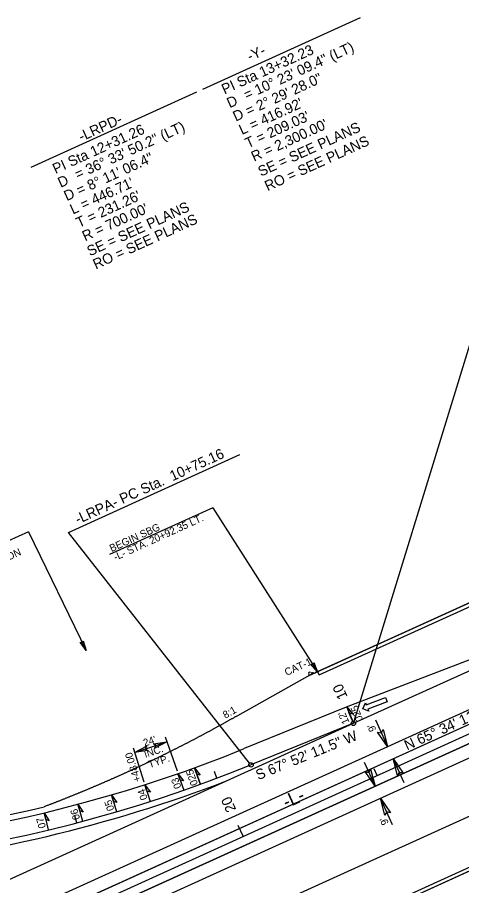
# Model space of a CAD drawing. Extents: x 2242984 to 2250974, y 661492 to 664681.
# Drawn here: x 2248440 to 2248742, y 663168 to 663758 of the extents above; entities that cross this region are included whole.
import ezdxf

# ---------------------------------------------------------------- set-up
doc = ezdxf.new("R2010")
doc.units = 0
for name, color, linetype in [('Prop Conc Shoulder Berm Gutter', 7, 'Continuous'), ('Prop Dimension', 7, 'Continuous'), ('Prop Dimension Text', 7, 'Continuous'), ('Prop DSN Text', 7, 'Continuous'), ('Prop EOT', 7, 'Continuous'), ('Prop Guardrail', 7, 'Continuous'), ('Prop Guardrail Anchor Unit CELL', 7, 'Continuous'), ('Prop Horizontal Alignment', 7, 'Continuous'), ('Prop Horizontal Alignment Curve and Spiral Data', 7, 'Continuous'), ('Prop Horizontal Alignment Direction Label', 7, 'Continuous'), ('Prop Horizontal Alignment Station Label', 7, 'Continuous'), ('Prop Horizontal Alignment Tick Label', 7, 'Continuous'), ('Prop Horizontal Alignment Tick Large', 7, 'Continuous'), ('Prop Horizontal Alignment Tick Small', 7, 'Continuous'), ('Prop Lane Arrow CELL', 7, 'Continuous'), ('Prop Lane Lines', 7, 'Continuous'), ('Prop Paved Shoulder', 7, 'Continuous'), ('Prop Superelevation  Arrow CELL', 7, 'Continuous'), ('Prop Superelevation Label', 7, 'Continuous'), ('Prop Terminator CELL', 7, 'Continuous'), ('Scratch_Level_6', 7, 'Continuous'), ('Scratch_Level_8', 7, 'Continuous'), ('Typical Terminator CELL', 7, 'Continuous')]:
    doc.layers.add(name, color=color, linetype=linetype)

# ---------------------------------------------------------------- blocks, each defined once
blk = doc.blocks.new('TERMINATOR')
at = {"layer": 'Typical Terminator CELL'}
blk.add_lwpolyline([(-0.469, 0.081), (0, 0), (-0.471, -0.083), (-0.411, 0)], close=True, dxfattribs=at)

msp = doc.modelspace()

# ---------------------------------------------------------------- linework, layer by layer
at = {"layer": 'Prop Conc Shoulder Berm Gutter'}
for p, q in [((2248644.9, 663311.13), (2248856.16, 663407.1)), ((2248643.94, 663313.26), (2248644.9, 663311.13)), ((2248645.24, 663134.09), (2248878.26, 663239.94))]:
    msp.add_line(p, q, dxfattribs=at)
at = {"layer": 'Prop Dimension'}
for p, q in [((2248668.27, 663278.18), (2248663.75, 663289.3)), ((2248683.23, 663280.59), (2248691.5, 663262.37)), ((2248540.32, 663268.91), (2248548.38, 663245.78)), ((2248518.51, 663261.48), (2248525.92, 663238.35)), ((2248702.68, 663237.75), (2248695.22, 663254.18)), ((2248675.51, 663251.85), (2248682.97, 663235.43)), ((2248694.89, 663209.19), (2248686.69, 663227.24))]:
    msp.add_line(p, q, dxfattribs=at)
msp.add_arc((2248237.01, 664139.15), 925, 287.78265, 289.21505, dxfattribs=at)
at = {"layer": 'Prop DSN Text'}
for p, q in [((2248572.63, 663424.84), (2248502.57, 663392.92)), ((2248572.63, 663424.84), (2248643.94, 663313.26)), ((2248447.47, 663408.55), (2248359.33, 663368.39)), ((2248447.47, 663408.55), (2248486.57, 663327.68))]:
    msp.add_line(p, q, dxfattribs=at)
at = {"layer": 'Prop EOT'}
for p, q in [((2248200.21, 663039.2), (2249433.89, 663599.6)), ((2248212.61, 663011.89), (2249446.3, 663572.29)), ((2248401.88, 663058.32), (2249188.04, 663415.44)), ((2248850.37, 663360.9), (2248663.29, 663289.12)), ((2248663.3, 663289.11), (2248594.13, 663260.98))]:
    msp.add_line(p, q, dxfattribs=at)
msp.add_arc((2248237.01, 664139.15), 948, 264.58168, 292.13013, dxfattribs=at)
at = {"layer": 'Prop Guardrail'}
for p, q in [((2248871.49, 663416.62), (2248643.94, 663313.26)), ((2248855.32, 663313.72), (2247994.71, 662922.79)), ((2248855.32, 663313.72), (2247994.71, 662922.79)), ((2247989.75, 662933.71), (2248810.53, 663306.55)), ((2247989.75, 662933.71), (2248810.53, 663306.55)), ((2248646.2, 663131.96), (2248885.14, 663240.5))]:
    msp.add_line(p, q, dxfattribs=at)
at = {"layer": 'Prop Guardrail Anchor Unit CELL'}
for p, q in [((2248639.22, 663312.85), (2248640.18, 663312.32)), ((2248640.14, 663312.42), (2248640.77, 663312.71)), ((2248640.47, 663311.68), (2248640.77, 663312.71)), ((2248643.94, 663313.26), (2248640.71, 663311.79)), ((2248640.77, 663312.71), (2248641.11, 663311.97)), ((2248642.97, 663313.7), (2248643.61, 663313.99)), ((2248643.3, 663312.97), (2248642.97, 663313.7)), ((2248643.94, 663313.26), (2248642.97, 663313.7)), ((2248643.3, 663312.97), (2248643.61, 663313.99)), ((2248643.94, 663313.26), (2248643.3, 663312.97)), ((2248643.61, 663313.99), (2248643.94, 663313.26)), ((2248640.71, 663311.79), (2248639.15, 663311.08)), ((2248640.47, 663311.68), (2248640.14, 663312.42)), ((2248641.11, 663311.97), (2248640.14, 663312.42)), ((2248641.11, 663311.97), (2248640.47, 663311.68)), ((2248640.59, 663311.74), (2248640.71, 663311.79)), ((2248640.62, 663312.19), (2248642.52, 663312.61))]:
    msp.add_line(p, q, dxfattribs=at)
msp.add_ellipse((2248638.74, 663311.99), major_axis=(0.411, -0.904), ratio=0.995379, start_param=2.210226, end_param=6.283185, dxfattribs=at)
at = {"layer": 'Prop Horizontal Alignment'}
for p, q in [((2247500.8, 662705.02), (2249793.08, 663746.29)), ((2248668.27, 663278.18), (2248598.65, 663249.87))]:
    msp.add_line(p, q, dxfattribs=at)
msp.add_arc((2248237.01, 664139.15), 960, 261.59641, 292.13013, dxfattribs=at)
at = {"layer": 'Prop Horizontal Alignment Station Label'}
for p, q in [((2248565.88, 663709.6), (2248673.03, 663758.42)), ((2248449.37, 663656.46), (2248561.96, 663707.76)), ((2248668.71, 663279.62), (2248748.29, 663538.62)), ((2248474.68, 663408.03), (2248591, 663461.04)), ((2248597.73, 663251.05), (2248474.68, 663408.03))]:
    msp.add_line(p, q, dxfattribs=at)
for centre in [(2248668.27, 663278.18), (2248598.65, 663249.87)]:
    msp.add_circle(centre, 1.5, dxfattribs=at)
at = {"layer": 'Prop Horizontal Alignment Tick Large'}
for p, q in [((2248668.27, 663278.18), (2248665.26, 663285.59)), ((2248593.36, 663201.31), (2248590.05, 663208.6))]:
    msp.add_line(p, q, dxfattribs=at)
at = {"layer": 'Prop Horizontal Alignment Tick Small'}
for p, q in [((2248575.52, 663240.81), (2248573.76, 663245.49)), ((2248684.4, 663242.67), (2248682.34, 663247.23)), ((2248480.28, 663210.48), (2248479.01, 663215.32))]:
    msp.add_line(p, q, dxfattribs=at)
at = {"layer": 'Prop Lane Arrow CELL'}
for p, q in [((2248677, 663290.82), (2248690.1, 663295.76)), ((2248690.1, 663295.76), (2248691.26, 663292.68)), ((2248674.65, 663288.11), (2248676.47, 663292.22)), ((2248676.47, 663292.22), (2248677, 663290.82)), ((2248691.26, 663292.68), (2248678.17, 663287.73)), ((2248678.7, 663286.33), (2248674.65, 663288.11)), ((2248678.17, 663287.73), (2248678.7, 663286.33))]:
    msp.add_line(p, q, dxfattribs=at)
at = {"layer": 'Prop Lane Lines'}
for p, q in [((2248668.27, 663278.18), (2248850.37, 663360.9)), ((2248304.14, 663112.77), (2248668.27, 663278.18))]:
    msp.add_line(p, q, dxfattribs=at)
msp.add_arc((2248237.01, 664139.15), 964, 275.75472, 290.97015, dxfattribs=at)
at = {"layer": 'Prop Paved Shoulder'}
for p, q in [((2248638.25, 663310.67), (2248855.2, 663409.22)), ((2248203.91, 663031), (2248894.79, 663344.83)), ((2248208.89, 663020.08), (2248895.78, 663332.1)), ((2248646.2, 663131.96), (2248879.23, 663237.81))]:
    msp.add_line(p, q, dxfattribs=at)
msp.add_arc((2248237.01, 664139.15), 944, 264.58097, 283.54456, dxfattribs=at)
for points in [[(2248638.25, 663310.67), (2248637.45, 663310.22), (2248636.64, 663309.77), (2248635.84, 663309.32), (2248635.03, 663308.87), (2248634.22, 663308.42), (2248633.42, 663307.97), (2248632.61, 663307.52), (2248631.81, 663307.06), (2248631, 663306.61), (2248630.19, 663306.16), (2248629.39, 663305.71), (2248628.58, 663305.26), (2248627.78, 663304.81), (2248626.97, 663304.36), (2248626.17, 663303.91), (2248625.36, 663303.45), (2248624.55, 663303), (2248623.75, 663302.55), (2248622.94, 663302.1), (2248622.14, 663301.65), (2248621.33, 663301.2), (2248620.53, 663300.75), (2248619.72, 663300.3), (2248618.91, 663299.84), (2248618.11, 663299.39), (2248617.3, 663298.94), (2248616.5, 663298.49), (2248615.69, 663298.04), (2248614.89, 663297.59), (2248614.08, 663297.14), (2248613.27, 663296.69), (2248612.47, 663296.23), (2248611.66, 663295.78), (2248610.86, 663295.33), (2248610.05, 663294.88), (2248609.24, 663294.43), (2248608.44, 663293.98), (2248607.63, 663293.53), (2248606.83, 663293.08), (2248606.02, 663292.62), (2248605.22, 663292.17), (2248604.41, 663291.72), (2248603.6, 663291.27), (2248602.8, 663290.82), (2248601.99, 663290.37), (2248601.19, 663289.92), (2248600.38, 663289.47), (2248599.58, 663289.01), (2248598.77, 663288.56), (2248597.96, 663288.11), (2248597.16, 663287.66), (2248596.35, 663287.21), (2248595.55, 663286.76), (2248594.74, 663286.31), (2248593.94, 663285.86), (2248593.13, 663285.4), (2248592.32, 663284.95), (2248591.52, 663284.5), (2248590.71, 663284.05), (2248589.91, 663283.6), (2248589.1, 663283.15), (2248588.29, 663282.7), (2248587.49, 663282.25), (2248586.68, 663281.79), (2248585.88, 663281.34), (2248585.1, 663280.9), (2248584.32, 663280.47), (2248583.55, 663280.03), (2248582.77, 663279.59), (2248581.99, 663279.16), (2248581.21, 663278.72), (2248580.43, 663278.29), (2248579.65, 663277.85), (2248578.87, 663277.42)], [(2248578.87, 663277.42), (2248578.09, 663276.99), (2248577.31, 663276.56), (2248576.53, 663276.13), (2248575.75, 663275.69), (2248574.97, 663275.27), (2248574.18, 663274.84), (2248573.4, 663274.41), (2248572.61, 663273.98), (2248571.83, 663273.55), (2248571.04, 663273.13), (2248570.26, 663272.7), (2248569.47, 663272.28), (2248568.69, 663271.85), (2248567.9, 663271.43), (2248567.11, 663271.01), (2248566.32, 663270.59), (2248565.53, 663270.17), (2248564.74, 663269.75), (2248563.95, 663269.33), (2248563.16, 663268.91), (2248562.37, 663268.49), (2248561.58, 663268.07), (2248560.79, 663267.66), (2248560, 663267.24), (2248559.21, 663266.82), (2248558.41, 663266.41), (2248557.62, 663266), (2248556.82, 663265.58), (2248556.03, 663265.17), (2248555.23, 663264.76), (2248554.44, 663264.35), (2248553.64, 663263.94), (2248552.85, 663263.53), (2248552.05, 663263.12), (2248551.25, 663262.71), (2248550.45, 663262.3), (2248549.65, 663261.9), (2248548.85, 663261.49), (2248548.05, 663261.09), (2248547.25, 663260.68), (2248546.45, 663260.28), (2248545.65, 663259.87), (2248544.85, 663259.47), (2248544.05, 663259.07), (2248543.25, 663258.67), (2248542.44, 663258.27), (2248541.64, 663257.87), (2248540.83, 663257.47), (2248540.03, 663257.07), (2248539.23, 663256.68), (2248538.42, 663256.28), (2248537.61, 663255.88), (2248536.81, 663255.49), (2248536, 663255.1), (2248535.19, 663254.7), (2248534.38, 663254.31), (2248533.58, 663253.92), (2248532.77, 663253.53), (2248531.96, 663253.14), (2248531.15, 663252.75), (2248530.34, 663252.36), (2248529.53, 663251.97), (2248528.72, 663251.58), (2248527.9, 663251.19), (2248527.09, 663250.81), (2248526.28, 663250.42), (2248525.47, 663250.04), (2248524.65, 663249.65), (2248523.84, 663249.27), (2248523.02, 663248.89), (2248522.21, 663248.51), (2248521.39, 663248.13), (2248520.58, 663247.75), (2248519.76, 663247.37)], [(2248519.76, 663247.37), (2248518.94, 663246.99), (2248518.13, 663246.61), (2248517.31, 663246.23), (2248516.49, 663245.86), (2248515.67, 663245.48), (2248514.85, 663245.11), (2248514.03, 663244.73), (2248513.21, 663244.36), (2248512.39, 663243.99), (2248511.57, 663243.61), (2248510.75, 663243.24), (2248509.93, 663242.87), (2248509.1, 663242.5), (2248508.28, 663242.13), (2248507.46, 663241.77), (2248506.63, 663241.4), (2248505.81, 663241.03), (2248504.99, 663240.67), (2248504.16, 663240.3), (2248503.33, 663239.94), (2248502.51, 663239.57), (2248501.68, 663239.21), (2248500.86, 663238.85), (2248500.03, 663238.49), (2248499.2, 663238.13), (2248498.37, 663237.77), (2248497.54, 663237.41), (2248496.71, 663237.05), (2248495.88, 663236.69), (2248495.05, 663236.34), (2248494.22, 663235.98), (2248493.39, 663235.62), (2248492.56, 663235.27), (2248491.73, 663234.92), (2248490.9, 663234.56), (2248490.06, 663234.21), (2248489.23, 663233.86), (2248488.4, 663233.51), (2248487.56, 663233.16), (2248486.73, 663232.81), (2248485.89, 663232.46), (2248485.06, 663232.11), (2248484.22, 663231.77), (2248483.39, 663231.42), (2248482.55, 663231.08), (2248481.71, 663230.73), (2248480.87, 663230.39), (2248480.04, 663230.04), (2248479.2, 663229.7), (2248478.36, 663229.36), (2248477.52, 663229.02), (2248476.68, 663228.68), (2248475.84, 663228.34), (2248475, 663228), (2248474.16, 663227.67), (2248473.32, 663227.33), (2248472.47, 663226.99), (2248471.63, 663226.66), (2248470.79, 663226.32), (2248469.95, 663225.99), (2248469.1, 663225.66), (2248468.26, 663225.32), (2248467.41, 663224.99), (2248466.57, 663224.66), (2248465.72, 663224.33), (2248464.88, 663224), (2248464.03, 663223.68), (2248463.19, 663223.35), (2248462.34, 663223.02), (2248461.49, 663222.7), (2248460.64, 663222.37), (2248459.79, 663222.05), (2248458.1, 663221.4)]]:
    msp.add_spline(points, degree=3, dxfattribs=at)
at = {"layer": 'Prop Superelevation  Arrow CELL'}
for p, q in [((2248663.75, 663289.3), (2248668.27, 663278.18)), ((2248560.18, 663247.93), (2248564.27, 663236.65)), ((2248549.01, 663243.96), (2248552.96, 663232.63)), ((2248526.54, 663236.44), (2248530.2, 663225.01)), ((2248503.88, 663229.48), (2248507.26, 663217.97)), ((2248481.06, 663223.1), (2248484.15, 663211.5)), ((2248458.08, 663217.28), (2248460.88, 663205.61))]:
    msp.add_line(p, q, dxfattribs=at)
for points in [[(2248663.75, 663289.3), (2248667.87, 663284.49), (2248665.5, 663285.01)], [(2248560.18, 663247.93), (2248564.1, 663242.97), (2248561.75, 663243.58)], [(2248549.01, 663243.96), (2248552.87, 663238.95), (2248550.53, 663239.59)], [(2248526.54, 663236.44), (2248530.27, 663231.34), (2248527.95, 663232.04)], [(2248503.88, 663229.48), (2248507.49, 663224.29), (2248505.18, 663225.05)], [(2248481.06, 663223.1), (2248484.54, 663217.81), (2248482.25, 663218.63)], [(2248458.08, 663217.28), (2248461.43, 663211.92), (2248459.16, 663212.79)]]:
    msp.add_lwpolyline(points, close=True, dxfattribs=at)
at = {"layer": 'Prop Superelevation Label'}
msp.add_line((2248564.27, 663236.65), (2248560.18, 663247.93), dxfattribs=at)
at = {"layer": 'Prop Terminator CELL'}
for points in [[(2248484.68, 663334.26), (2248486.57, 663327.68), (2248482.54, 663333.27), (2248483.99, 663333.01)], [(2248641.28, 663319.57), (2248643.94, 663313.26), (2248639.27, 663318.33), (2248640.75, 663318.25)], [(2248532.43, 663264.22), (2248541.44, 663265.68), (2248533.4, 663261.22), (2248533.97, 663263.11)], [(2248528.55, 663259.65), (2248519.51, 663258.34), (2248527.62, 663262.66), (2248527.02, 663260.79)]]:
    msp.add_lwpolyline(points, close=True, dxfattribs=at)
at = {"layer": 'Scratch_Level_6'}
for p, q in [((2248643.9, 663313.35), (2248888.59, 663424.5)), ((2248639.11, 663311.17), (2248643.9, 663313.35)), ((2248902.31, 663248.19), (2248646.24, 663131.87))]:
    msp.add_line(p, q, dxfattribs=at)
at = {"layer": 'Scratch_Level_8'}
for p, q in [((2248643.9, 663313.34), (2248866.79, 663414.59)), ((2248880.54, 663238.31), (2248646.24, 663131.88))]:
    msp.add_line(p, q, dxfattribs=at)

# ---------------------------------------------------------------- block references
at = {"layer": 'Prop Dimension', "xscale": 25}
for p, yscale, rotation in [((2248691.5, 663262.37), 25, -65.56987410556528), ((2248695.22, 663254.18), 25.00000000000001, 114.43012589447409), ((2248682.97, 663235.43), 25, -65.56987410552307), ((2248686.69, 663227.24), 25, 114.43012589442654)]:
    msp.add_blockref('TERMINATOR', p, dxfattribs=dict(at, yscale=yscale, rotation=rotation))

# ---------------------------------------------------------------- texts
at = {"layer": 'Prop Dimension'}
for s, rotation, p in [("9'", 114.43013, (2248683.99, 663273.79)), ("24'", 18.49885, (2248526.37, 663262.35)), ('INC.', 18.49885, (2248526.89, 663254.61)), ('+48.00', 107.78265, (2248523.96, 663239.25)), ('TYP.', 18.49885, (2248529.81, 663247.68)), ("9'", 114.43013, (2248692.42, 663210.3))]:
    msp.add_text(s, height=5, rotation=rotation, dxfattribs=at).set_placement(p)
at = {"layer": 'Prop Dimension Text'}
for s, rotation, p in [('8:1', 29.24602, (2248581.23, 663281.23)), ("12'", 114.49794, (2248665.71, 663278.95))]:
    msp.add_text(s, height=5, rotation=rotation, dxfattribs=at).set_placement(p)
at = {"layer": 'Prop DSN Text'}
for s, p in [('-L- STA. 20+92.35 LT.', (2248506.62, 663388.7)), ('BEGIN SBG', (2248503.9, 663394.66)), ('DURING CONSTRUCTION', (2248368.26, 663358.92))]:
    msp.add_text(s, height=5, rotation=24.49794, dxfattribs=at).set_placement(p)
at = {"layer": 'Prop Guardrail Anchor Unit CELL'}
msp.add_text('CAT-1', height=5, rotation=24.43013, dxfattribs=at).set_placement((2248622.88, 663310.36))
at = {"layer": 'Prop Horizontal Alignment Curve and Spiral Data'}
for s, height, rotation, p in [('PI Sta 13+32.23', 7, 24.49794, (2248580.64, 663705.94)), ('= 10%%d 23\' 09.4" (LT)', 7, 24.49794, (2248595.74, 663702.16)), ('-Y-', 7, 24.49794, (2248597.89, 663728.38)), ('D = 2%%d 29\' 28.0"', 7, 24.49794, (2248588.32, 663687.46)), ('D', 7, 24.49794, (2248584.17, 663696.56)), ("L = 416.92'", 7, 24.49794, (2248592.47, 663678.36)), ('-LRPD-', 7, 24.49794, (2248483.4, 663673.8)), ("T = 209.03'", 7, 24.49794, (2248596.61, 663669.26)), ('PI Sta 12+31.26', 7, 24.49794, (2248465.78, 663651.82)), ('= 36%%d 33\' 50.2" (LT)', 7, 24.49794, (2248480.88, 663648.04)), ("R = 2,300.00'", 7, 24.49794, (2248600.76, 663660.16)), ('SE = SEE PLANS', 7, 24.49794, (2248605.4, 663649.99)), ('RO = SEE PLANS', 7, 24.49794, (2248609.91, 663640.09)), ('D = 8%%d 11\' 06.4"', 7, 24.49794, (2248473.46, 663633.34)), ('D', 7, 24.49794, (2248469.31, 663642.44)), ("L = 446.71'", 7, 24.49794, (2248477.61, 663624.24)), ("T = 231.26'", 7, 24.49794, (2248481.75, 663615.14)), ("R = 700.00'", 7, 24.49794, (2248485.9, 663606.04)), ('SE = SEE PLANS', 7, 24.49794, (2248489.15, 663595.79)), ('RO = SEE PLANS', 7, 24.49794, (2248493.21, 663586.87)), ('-L-', 9, 24.43013, (2248622.69, 663220.12))]:
    msp.add_text(s, height=height, rotation=rotation, dxfattribs=at).set_placement(p)
at = {"layer": 'Prop Horizontal Alignment Direction Label'}
for s, rotation, p in [('N 65%%d 34\' 11.5" E', 24.43013, (2248704.77, 663259.62)), ('S 67%%d 52\' 11.5" W', 22.13013, (2248603.61, 663239.45))]:
    msp.add_text(s, height=7, rotation=rotation, dxfattribs=at).set_placement(p)
at = {"layer": 'Prop Horizontal Alignment Station Label'}
msp.add_text('-LRPA- PC Sta.  10+75.16', height=7, rotation=24.49794, dxfattribs=at).set_placement((2248480.98, 663413.47))
at = {"layer": 'Prop Horizontal Alignment Tick Label'}
for s, p in [('10', (2248664.51, 663296.26)), ('20', (2248588.74, 663219.57))]:
    msp.add_text(s, height=7, rotation=114.43013, dxfattribs=at).set_placement(p)
at = {"layer": 'Prop Superelevation Label'}
for s, rotation, p in [('025', 112.13013, (2248674.98, 663280.56)), ('025', 109.93125, (2248562.74, 663236.8)), ('03', 111.17491, (2248551.5, 663234.76)), ('04', 109.74251, (2248528.57, 663227)), ('05', 108.31012, (2248505.89, 663219.5)), ('06', 106.87773, (2248482.61, 663213.35)), ('07', 105.44533, (2248459.38, 663207.46))]:
    msp.add_text(s, height=5, rotation=rotation, dxfattribs=at).set_placement(p)

doc.saveas('drawing.dxf')
